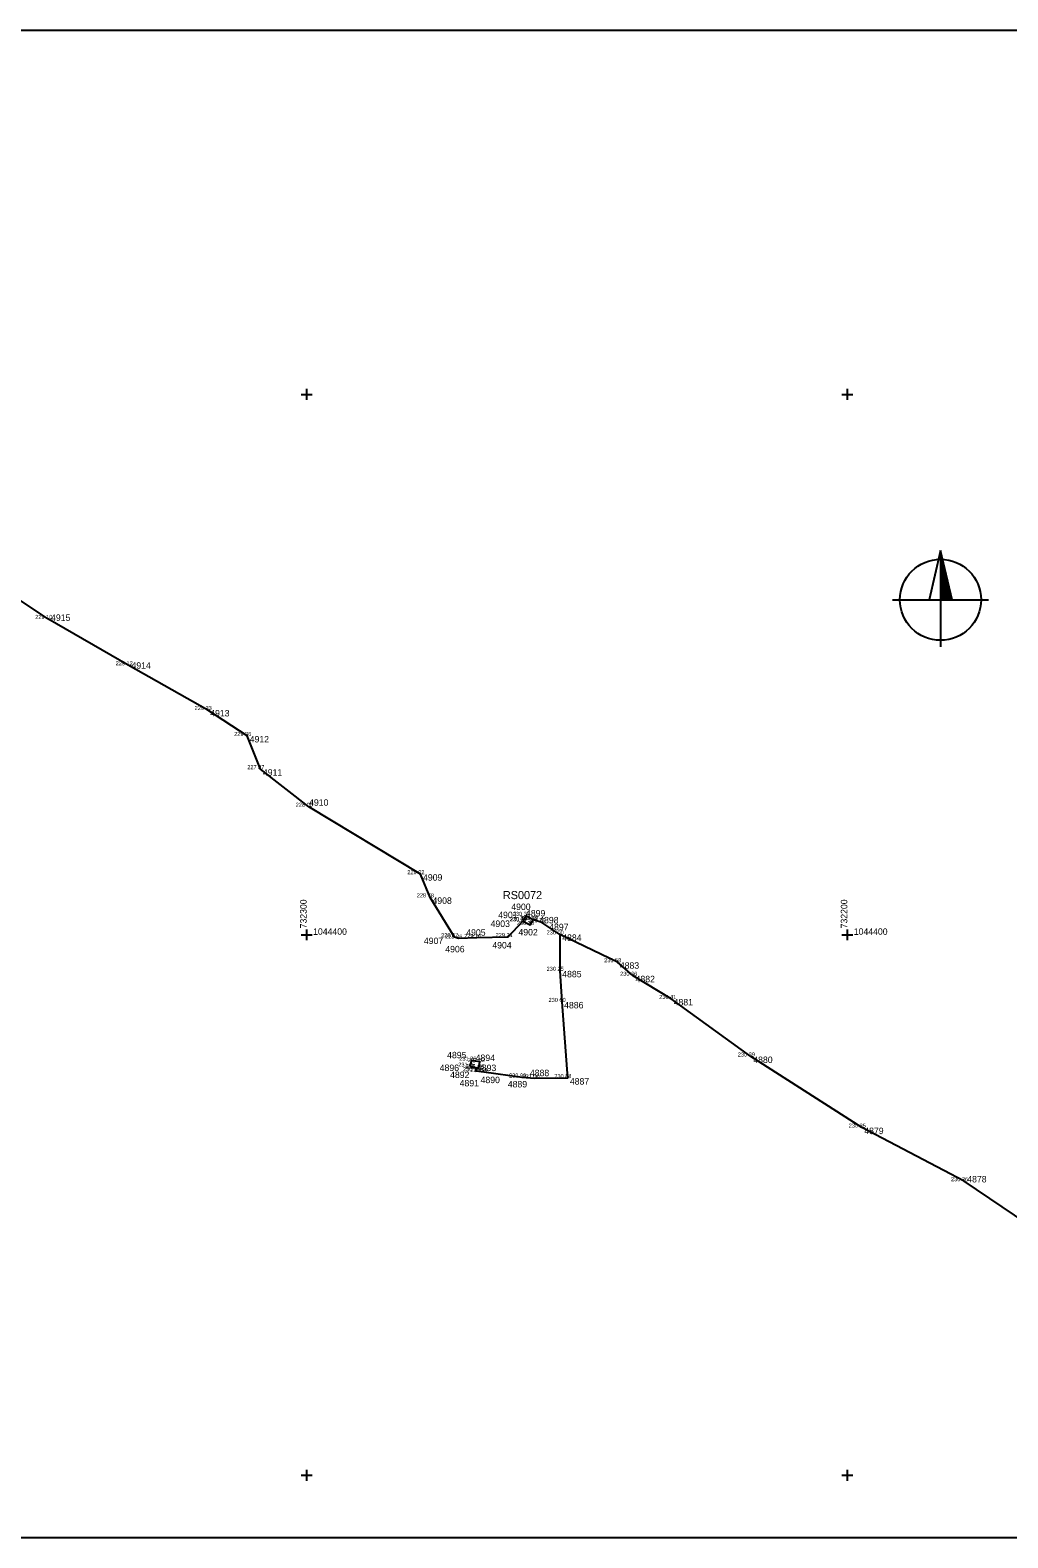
# Model space of a CAD drawing. Extents: x -736532 to -730799, y -1045301 to -1042399.
# Drawn here: x -732351.1 to -732170.3, y -1044511.6 to -1044232.6 of the extents above; entities that cross this region are included whole.
import ezdxf

# ---------------------------------------------------------------- set-up
doc = ezdxf.new("R2010")
doc.units = 0
for name, color, linetype in [('Vrstva 23', 7, 'Continuous'), ('Vrstva 25', 7, 'Continuous'), ('Vrstva 26', 7, 'Continuous'), ('Vrstva 50', 7, 'Continuous'), ('Vrstva 60', 7, 'Continuous'), ('Vrstva 61', 7, 'Continuous'), ('Vrstva 62', 7, 'Continuous'), ('Vrstva 63', 7, 'Continuous')]:
    doc.layers.add(name, color=color, linetype=linetype)

msp = doc.modelspace()

# ---------------------------------------------------------------- linework, layer by layer
at = {"layer": 'Vrstva 23'}
for points in [[(-732258.12, -1044397.22), (-732259.44, -1044396.49), (-732259.99, -1044397.44), (-732258.67, -1044398.17), (-732258.12, -1044397.22)], [(-732268.17, -1044424.64), (-732267.99, -1044423.52), (-732269.59, -1044423.27), (-732269.77, -1044424.39), (-732268.17, -1044424.64)]]:
    msp.add_lwpolyline(points, dxfattribs=at)
at = {"layer": 'Vrstva 26'}
for points in [[(-732260.07, -1044397.52), (-732262.81, -1044400.41), (-732268.53, -1044400.58), (-732271.92, -1044400.7), (-732272.66, -1044400.44), (-732277.17, -1044393.07), (-732278.91, -1044388.78), (-732299.57, -1044376.31), (-732308.53, -1044369.35), (-732310.97, -1044363.2), (-732318.28, -1044358.4), (-732332.98, -1044350.12), (-732347.85, -1044341.55), (-732356.08, -1044336.04)], [(-732058.19, -1044509.99), (-732067.72, -1044506.05), (-732068.76, -1044505.26), (-732076.62, -1044501.94), (-732085.52, -1044497.83), (-732089.06, -1044496.15), (-732091.27, -1044495.1), (-732094.96, -1044493.35), (-732104.4, -1044488.86), (-732111.63, -1044485.87), (-732114.06, -1044483.14), (-732129.26, -1044476.59), (-732136.89, -1044472.92), (-732138.44, -1044470.19), (-732164.35, -1044455.06), (-732178.4, -1044445.59), (-732197.3, -1044435.67), (-732217.83, -1044422.52), (-732232.56, -1044411.86), (-732239.6, -1044407.58), (-732242.52, -1044405.07), (-732253.17, -1044399.93), (-732256.53, -1044397.71), (-732258.03, -1044397.24)], [(-732253.17, -1044399.93), (-732253.17, -1044406.66), (-732252.82, -1044412.41), (-732251.76, -1044426.51), (-732257.88, -1044426.56), (-732260.11, -1044426.4), (-732267.25, -1044425.4), (-732268.64, -1044425.23), (-732268.65, -1044424.74)]]:
    msp.add_lwpolyline(points, dxfattribs=at)
at = {"layer": 'Vrstva 50'}
for p, q in [((-732182.76, -1044328.9), (-732184.89, -1044338)), ((-732180.63, -1044338), (-732182.76, -1044328.9)), ((-732182.76, -1044328.9), (-732182.76, -1044346.71)), ((-732182.76, -1044329.25), (-732182.68, -1044329.25)), ((-732182.76, -1044329.38), (-732182.65, -1044329.38)), ((-732182.76, -1044329.5), (-732182.62, -1044329.5)), ((-732182.76, -1044329.63), (-732182.59, -1044329.63)), ((-732182.76, -1044329.75), (-732182.56, -1044329.75)), ((-732182.76, -1044329.88), (-732182.53, -1044329.88)), ((-732182.76, -1044330), (-732182.5, -1044330)), ((-732182.76, -1044330.13), (-732182.47, -1044330.13)), ((-732182.76, -1044330.25), (-732182.44, -1044330.25)), ((-732182.76, -1044330.38), (-732182.41, -1044330.38)), ((-732182.76, -1044330.5), (-732182.38, -1044330.5)), ((-732182.76, -1044330.63), (-732182.35, -1044330.63)), ((-732182.76, -1044330.75), (-732182.33, -1044330.75)), ((-732182.76, -1044330.88), (-732182.3, -1044330.88)), ((-732182.76, -1044331), (-732182.27, -1044331)), ((-732182.76, -1044331.13), (-732182.24, -1044331.13)), ((-732182.76, -1044331.25), (-732182.21, -1044331.25)), ((-732182.76, -1044331.38), (-732182.18, -1044331.38)), ((-732182.76, -1044331.5), (-732182.15, -1044331.5)), ((-732182.76, -1044331.63), (-732182.12, -1044331.63)), ((-732182.76, -1044331.75), (-732182.09, -1044331.75)), ((-732182.76, -1044331.88), (-732182.06, -1044331.88)), ((-732182.76, -1044332), (-732182.03, -1044332)), ((-732182.76, -1044332.13), (-732182, -1044332.13)), ((-732182.76, -1044332.25), (-732181.97, -1044332.25)), ((-732182.76, -1044332.38), (-732181.95, -1044332.38)), ((-732182.76, -1044332.5), (-732181.92, -1044332.5)), ((-732182.76, -1044332.63), (-732181.89, -1044332.63)), ((-732182.76, -1044332.75), (-732181.86, -1044332.75)), ((-732182.76, -1044332.88), (-732181.83, -1044332.88)), ((-732182.76, -1044333), (-732181.8, -1044333)), ((-732182.76, -1044333.13), (-732181.77, -1044333.13)), ((-732182.76, -1044333.25), (-732181.74, -1044333.25)), ((-732182.76, -1044333.38), (-732181.71, -1044333.38)), ((-732182.76, -1044333.5), (-732181.68, -1044333.5)), ((-732182.76, -1044333.63), (-732181.65, -1044333.63)), ((-732182.76, -1044333.75), (-732181.62, -1044333.75)), ((-732182.76, -1044333.88), (-732181.59, -1044333.88)), ((-732182.76, -1044334), (-732181.57, -1044334)), ((-732182.76, -1044334.13), (-732181.54, -1044334.13)), ((-732182.76, -1044334.25), (-732181.51, -1044334.25)), ((-732182.76, -1044334.38), (-732181.48, -1044334.38)), ((-732182.76, -1044334.5), (-732181.45, -1044334.5)), ((-732182.76, -1044334.63), (-732181.42, -1044334.63)), ((-732182.76, -1044334.75), (-732181.39, -1044334.75)), ((-732182.76, -1044334.88), (-732181.36, -1044334.88)), ((-732182.76, -1044335), (-732181.33, -1044335)), ((-732182.76, -1044335.13), (-732181.3, -1044335.13)), ((-732182.76, -1044335.25), (-732181.27, -1044335.25)), ((-732182.76, -1044335.38), (-732181.24, -1044335.38)), ((-732182.76, -1044335.5), (-732181.21, -1044335.5)), ((-732182.76, -1044335.63), (-732181.19, -1044335.63)), ((-732182.76, -1044335.75), (-732181.16, -1044335.75)), ((-732182.76, -1044335.88), (-732181.13, -1044335.88)), ((-732182.76, -1044336), (-732181.1, -1044336)), ((-732182.76, -1044336.13), (-732181.07, -1044336.13)), ((-732182.76, -1044336.25), (-732181.04, -1044336.25)), ((-732182.76, -1044336.38), (-732181.01, -1044336.38)), ((-732182.76, -1044336.5), (-732180.98, -1044336.5)), ((-732182.76, -1044336.63), (-732180.95, -1044336.63)), ((-732182.76, -1044336.75), (-732180.92, -1044336.75)), ((-732182.76, -1044336.88), (-732180.89, -1044336.88)), ((-732182.76, -1044337), (-732180.86, -1044337)), ((-732182.76, -1044337.13), (-732180.83, -1044337.13)), ((-732191.64, -1044338), (-732173.88, -1044338)), ((-732182.76, -1044337.25), (-732180.81, -1044337.25)), ((-732182.76, -1044337.38), (-732180.78, -1044337.38)), ((-732182.76, -1044337.5), (-732180.75, -1044337.5)), ((-732182.76, -1044337.63), (-732180.72, -1044337.63)), ((-732182.76, -1044337.75), (-732180.69, -1044337.75)), ((-732182.76, -1044337.88), (-732180.66, -1044337.88))]:
    msp.add_line(p, q, dxfattribs=at)
msp.add_circle((-732182.76, -1044338), 7.5, dxfattribs=at)
at = {"layer": 'Vrstva 60'}
for p, q in [((-732347.85, -1044341.55), (-732347.85, -1044341.55)), ((-732332.98, -1044350.12), (-732332.98, -1044350.12)), ((-732318.28, -1044358.4), (-732318.28, -1044358.4)), ((-732310.97, -1044363.2), (-732310.97, -1044363.2)), ((-732308.53, -1044369.35), (-732308.53, -1044369.35)), ((-732299.57, -1044376.31), (-732299.57, -1044376.31)), ((-732278.91, -1044388.78), (-732278.91, -1044388.78)), ((-732277.17, -1044393.07), (-732277.17, -1044393.07)), ((-732260.07, -1044397.52), (-732260.07, -1044397.52)), ((-732259.99, -1044397.44), (-732259.99, -1044397.44)), ((-732259.44, -1044396.49), (-732259.44, -1044396.49)), ((-732258.67, -1044398.17), (-732258.67, -1044398.17)), ((-732258.12, -1044397.22), (-732258.12, -1044397.22)), ((-732258.03, -1044397.24), (-732258.03, -1044397.24)), ((-732256.53, -1044397.71), (-732256.53, -1044397.71)), ((-732272.66, -1044400.44), (-732272.66, -1044400.44)), ((-732271.92, -1044400.7), (-732271.92, -1044400.7)), ((-732268.53, -1044400.58), (-732268.53, -1044400.58)), ((-732262.81, -1044400.41), (-732262.81, -1044400.41)), ((-732253.17, -1044399.93), (-732253.17, -1044399.93)), ((-732253.17, -1044406.66), (-732253.17, -1044406.66)), ((-732242.52, -1044405.07), (-732242.52, -1044405.07)), ((-732239.6, -1044407.58), (-732239.6, -1044407.58)), ((-732252.82, -1044412.41), (-732252.82, -1044412.41)), ((-732232.56, -1044411.86), (-732232.56, -1044411.86)), ((-732269.59, -1044423.27), (-732269.59, -1044423.27)), ((-732267.99, -1044423.52), (-732267.99, -1044423.52)), ((-732217.83, -1044422.52), (-732217.83, -1044422.52)), ((-732269.77, -1044424.39), (-732269.77, -1044424.39)), ((-732268.65, -1044424.74), (-732268.65, -1044424.74)), ((-732268.64, -1044425.23), (-732268.64, -1044425.23)), ((-732268.17, -1044424.64), (-732268.17, -1044424.64)), ((-732267.25, -1044425.4), (-732267.25, -1044425.4)), ((-732260.11, -1044426.4), (-732260.11, -1044426.4)), ((-732257.88, -1044426.56), (-732257.88, -1044426.56)), ((-732251.76, -1044426.51), (-732251.76, -1044426.51)), ((-732197.3, -1044435.67), (-732197.3, -1044435.67)), ((-732178.4, -1044445.59), (-732178.4, -1044445.59))]:
    msp.add_line(p, q, dxfattribs=at)
at = {"layer": 'Vrstva 61'}
for p, q in [((-732301, -1044300), (-732299, -1044300)), ((-732300, -1044299), (-732300, -1044301)), ((-732201, -1044300), (-732199, -1044300)), ((-732200, -1044299), (-732200, -1044301)), ((-732301, -1044400), (-732299, -1044400)), ((-732300, -1044399), (-732300, -1044401)), ((-732201, -1044400), (-732199, -1044400)), ((-732200, -1044399), (-732200, -1044401)), ((-732301, -1044500), (-732299, -1044500)), ((-732300, -1044499), (-732300, -1044501)), ((-732201, -1044500), (-732199, -1044500)), ((-732200, -1044499), (-732200, -1044501))]:
    msp.add_line(p, q, dxfattribs=at)
at = {"layer": 'Vrstva 63'}
msp.add_lwpolyline([(-732499.11, -1044232.61), (-732094.99, -1044232.61), (-732094.99, -1044511.57), (-732499.11, -1044511.57)], close=True, dxfattribs=at)

# ---------------------------------------------------------------- texts
at = {"layer": 'Vrstva 25'}
msp.add_text('RS0072', height=1.5, dxfattribs=at).set_placement((-732263.7, -1044393.39))
at = {"layer": 'Vrstva 61'}
for s, p in [(' 4915', (-732347.71, -1044341.91)), (' 4914', (-732332.84, -1044350.76)), (' 4913', (-732318.28, -1044359.59)), (' 4912', (-732310.97, -1044364.4)), (' 4911', (-732308.53, -1044370.55)), (' 4910', (-732299.99, -1044376.11)), (' 4909', (-732278.91, -1044389.98)), (' 4908', (-732277.17, -1044394.27)), (' 4901', (-732265.01, -1044396.92)), (' 4900', (-732262.59, -1044395.41)), (' 4899', (-732259.87, -1044396.6)), (' 4903', (-732266.42, -1044398.54)), (' 4898', (-732257.43, -1044397.88)), (' 4897', (-732255.58, -1044399.15)), (' 4907', (-732278.76, -1044401.71)), (' 4905', (-732270.92, -1044400.16)), (' 4904', (-732266.1, -1044402.52)), (' 4902', (-732261.27, -1044400.11)), (' 4884', (-732253.17, -1044401.13)), (' 4906', (-732274.8, -1044403.24)), (' 4885', (-732253.17, -1044407.86)), (' 4883', (-732242.52, -1044406.27)), (' 4882', (-732239.6, -1044408.78)), (' 4886', (-732252.82, -1044413.61)), (' 4881', (-732232.56, -1044413.06)), (' 4895', (-732274.46, -1044422.85)), (' 4894', (-732269.18, -1044423.35)), (' 4880', (-732217.83, -1044423.72)), (' 4896', (-732275.83, -1044425.2)), (' 4892', (-732273.91, -1044426.5)), (' 4893', (-732268.94, -1044425.21)), (' 4890', (-732268.27, -1044427.44)), (' 4888', (-732259.15, -1044426.15)), (' 4891', (-732272.14, -1044428.04)), (' 4889', (-732263.24, -1044428.23)), (' 4887', (-732251.76, -1044427.71)), (' 4879', (-732197.3, -1044436.87)), (' 4878', (-732178.26, -1044445.81))]:
    msp.add_text(s, height=1.2, dxfattribs=at).set_placement(p)
at = {"layer": 'Vrstva 62'}
for s, p in [('229 10 ', (-732350.19, -1044341.55)), ('229 12 ', (-732335.32, -1044350.12)), ('229 33 ', (-732320.71, -1044358.4)), ('229 36 ', (-732313.4, -1044363.2)), ('227 87 ', (-732310.98, -1044369.35)), ('228 00 ', (-732302.03, -1044376.31)), ('229 02 ', (-732281.37, -1044388.78)), ('228 78 ', (-732279.63, -1044393.07)), ('230 37 ', (-732261.87, -1044396.49)), ('230 39 ', (-732262.43, -1044397.44)), ('230 17 ', (-732262.39, -1044397.52)), ('230 38 ', (-732261.11, -1044398.17)), ('230 38 ', (-732260.56, -1044397.22)), ('230 19 ', (-732260.35, -1044397.24)), ('229 75 ', (-732258.99, -1044397.71)), ('228 87 ', (-732275.12, -1044400.44)), ('228 86 ', (-732274.36, -1044400.7)), ('229 10 ', (-732270.86, -1044400.58)), ('229 21 ', (-732265.05, -1044400.41)), ('230 00 ', (-732255.62, -1044399.93)), ('230 25 ', (-732255.62, -1044406.66)), ('230 58 ', (-732244.97, -1044405.07)), ('230 36 ', (-732242.02, -1044407.58)), ('230 60 ', (-732255.26, -1044412.41)), ('230 41 ', (-732234.79, -1044411.86)), ('231 25 ', (-732271.96, -1044424.39)), ('231 26 ', (-732271.77, -1044423.27)), ('231 32 ', (-732270.17, -1044423.52)), ('230 39 ', (-732220.26, -1044422.52)), ('230 99 ', (-732271.08, -1044425.23)), ('231 41 ', (-732270.63, -1044424.74)), ('231 24 ', (-732270.36, -1044424.64)), ('230 99 ', (-732269.7, -1044425.4)), ('230 90 ', (-732262.56, -1044426.4)), ('231 00 ', (-732260.08, -1044426.56)), ('230 88 ', (-732254.2, -1044426.51)), ('230 35 ', (-732199.74, -1044435.67)), ('230 36 ', (-732180.82, -1044445.59))]:
    msp.add_text(s, height=0.75, dxfattribs=at).set_placement(p)
at = {"layer": 'Vrstva 63'}
for s, p in [('732300', (-732300, -1044398.8)), ('732200', (-732200, -1044398.8))]:
    msp.add_text(s, height=1.2, rotation=90, dxfattribs=at).set_placement(p)
for p in [(-732298.8, -1044400), (-732198.8, -1044400)]:
    msp.add_text('1044400', height=1.2, dxfattribs=at).set_placement(p)

doc.saveas('drawing.dxf')
